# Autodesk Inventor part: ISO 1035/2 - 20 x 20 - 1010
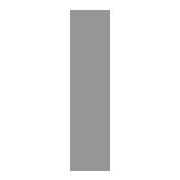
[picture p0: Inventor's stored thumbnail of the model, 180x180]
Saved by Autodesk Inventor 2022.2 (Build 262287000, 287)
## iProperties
IsCustomPart: 1
Created: 2021-02
Part Number: ISO 1035/2 - 20 x 20 - 1010
Material: Acciaio, Dolce
Description: Barre in acciaio laminate a caldo - Parte 2: barre quadre
Document SubType Name: Modeling
Standard: ISO 1035/2
Designer: 18907419
Standard Revision: First edition 1980-10-15
Standards Organization: ISO
Language: it-IT
Size Designation: 20x 20
Categories: <MemberInstance><Categories><Category DisplayName="Forme strutturali" InternalName="089c4875-fa83-4c05-b084-43b9cc11f5ed" Mnemonic="GRDR"><CategoryParameter Dis
Stock Number: 20x 20
Density: 7.85 g/cm^3
Appearance: Semilucidato
_CCFamilyMember: 168
_CCFamilyDisplayName: ISO 1035/2 - 1980 - Barre in acciaio laminate a caldo - Parte 2: barre quadre
_FrameMemberDoc: Frame Member File
_Version: 15.0.0
_GetPNFromCC: 1
G_L: 1010,000 mm
G_W: 20,000 mm
G_H: 20,000 mm
+6B59C954-9796-4C30-8DAD-3A38A1700938+CUTDETAIL1: Angolo retto 45,00 gr
+A2FAA2FC-754C-4FE4-BA2F-E865AD32149B+CUTDETAIL2: Angolo retto 45,00 gr
Author: 18907419
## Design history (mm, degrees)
node "Piano iniziale"
node "Piano finale"
sketch "Schizzo"
  geometry: L1 (10, -10)-(-10, -10); L2 (-10, -10)-(-10, 10); L3 (-10, 10)-(10, 10); L4 (10, 10)-(10, -10); L5 (-6, 0)-(8, 0); L6 (0, -30)-(0, 40); L7 (0, 54)-(0, -44) reference; L8 (-14, 0)-(14, 0) reference
  constraints: 12 end point, 2 collinear, 2 parallel, 1 horizontal, 1 perpendicular
  dimensions: "d0" = 20 distance between parallel lines of L3 L1 (= G_W); "d1" = 20 distance between parallel lines of L4 L2 (= G_H); "d4" = 10 distance between parallel lines of L6 L4 (= 0.5 x d1); "d5" = 10 distance between parallel lines of L5 L3 (= 0.5 x d0)
extrude "Corpo" new body sketch "Schizzo" stored distance "d2" = 1010 (= G_L); taper "d3" = 0 deg
node "Driven Length"
  sketch "Sketch3"
    geometry: L1 (0, 0)-(10, 0) reference
    constraints: 2 end point, 1 horizontal
  workplane "Work Plane3"
  sketch "Sketch4"
    geometry: L1 (-2, 0)-(12, 0) reference; L2 (-2, 1010)-(12, 1010) reference
    dimensions: "d9" = 1010 distance between parallel lines of L1 L2 (derived)
node "Piano di lavoro4"
feature "Divisione1"
node "Piano di lavoro5"
feature "Divisione2"
body "Solid1"
other parameters: "G_W" = 20 [user parameter; used in 1 equation term], "G_H" = 20 [user parameter; used in 1 equation term], "G_L" = 1010 (= d9) [user parameter; used in 1 equation term], "G_OFFSET_START" = 0 [user parameter; used in 1 equation term], "d6" = 0 (computed from G_OFFSET_START), "d8" = 90 deg
